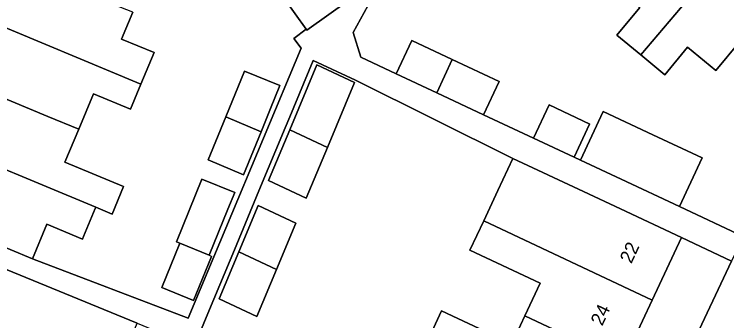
# Model space of a CAD drawing. Extents: x 159817 to 160765, y 380688 to 381638.
# Drawn here: x 160093.1 to 160145.9, y 381410.5 to 381433.2 of the extents above; entities that cross this region are included whole.
import ezdxf

# ---------------------------------------------------------------- set-up
doc = ezdxf.new("R2010")
doc.units = 0
for name, color, linetype in [('IMGEO_Erf', 7, 'Continuous'), ('IMGEO_Pand', 7, 'Continuous'), ('IMGEO_Pand_nummerreeks', 7, 'Continuous'), ('IMGEO_Voetpad_open', 7, 'Continuous')]:
    doc.layers.add(name, color=color, linetype=linetype)

msp = doc.modelspace()

# ---------------------------------------------------------------- linework, layer by layer
at = {"layer": 'IMGEO_Erf'}
for points in [[(160101.841, 381433.323), (160101.015, 381431.335), (160103.427, 381430.332), (160102.457, 381427.998), (160101.687, 381426.146), (160098.933, 381427.291), (160097.839, 381424.659), (160096.821, 381422.21), (160101.17, 381420.402), (160100.324, 381418.367), (160099.098, 381418.877), (160099.058, 381418.781), (160098.81, 381418.184), (160098.2, 381416.715), (160098.118, 381416.517), (160095.484, 381417.613), (160094.422, 381415.059), (160105.95, 381410.653), (160114.336, 381430.674), (160113.796, 381431.38), (160114.705, 381432.077), (160113.066, 381434.377)], [(160119.545, 381434.316), (160118.188, 381431.819), (160118.748, 381429.996), (160121.379, 381428.765), (160122.529, 381431.223), (160125.539, 381429.814), (160129.015, 381428.187), (160127.865, 381425.73), (160131.569, 381423.996), (160132.719, 381426.454), (160135.731, 381425.044), (160135.722, 381425.033), (160134.578, 381422.588), (160135.039, 381422.372), (160136.724, 381425.973), (160140.415, 381424.245), (160144.076, 381422.532), (160142.391, 381418.932), (160147.119, 381416.719), (160155.458, 381434.407)], [(160149.436, 381434.021), (160150.464, 381433.17), (160149.636, 381431.574), (160147.912, 381430.315), (160146.877, 381431.172), (160145.087, 381429.011), (160142.991, 381430.748), (160141.294, 381428.698), (160139.52, 381430.167), (160137.746, 381431.636), (160139.437, 381433.679)], [(160123.716, 381408.999), (160124.748, 381411.204), (160129.948, 381408.769), (160130.912, 381410.828), (160132.047, 381413.254), (160126.85, 381415.687), (160127.868, 381417.861), (160128.924, 381420.116), (160130.033, 381422.485), (160118.359, 381428.29), (160115.237, 381429.759), (160113.495, 381425.585), (160113.154, 381424.768), (160111.198, 381420.081), (160109.38, 381415.724), (160107.54, 381411.312), (160105.673, 381406.838)], [(160105.356, 381328.134), (160146.257, 381414.891), (160142.531, 381416.636), (160140.36, 381411.999), (160138.209, 381407.404), (160138.128, 381407.231), (160137.606, 381407.476), (160135.69, 381403.384), (160133.653, 381399.032), (160133.533, 381398.776), (160132.918, 381399.064), (160131.006, 381394.979), (160129.007, 381390.709), (160127.008, 381386.439), (160125.008, 381382.168), (160123.009, 381377.898), (160121.01, 381373.628), (160119.011, 381369.358), (160117.012, 381365.088)], [(160092.333, 381377.953), (160096.781, 381388.612), (160102.837, 381403.126), (160105.289, 381409.003), (160104.86, 381409.18), (160102.942, 381404.521), (160100.266, 381405.64), (160102.178, 381410.284), (160090.993, 381414.866)]]:
    msp.add_lwpolyline(points, dxfattribs=at)
for points in [[(160112.068, 381426.181), (160111.37, 381424.469), (160110.071, 381421.282), (160107.439, 381422.384), (160108.74, 381425.578), (160110.122, 381428.97), (160112.765, 381427.893)], [(160113.488, 381424.611), (160115.5, 381429.432), (160118.288, 381428.12), (160116.277, 381423.302), (160114.711, 381419.547), (160111.92, 381420.856)], [(160108.907, 381418.741), (160107.511, 381415.316), (160107.694, 381415.24), (160106.359, 381411.962), (160103.999, 381412.923), (160105.34, 381416.215), (160105.083, 381416.321), (160106.972, 381420.961), (160109.407, 381419.969)], [(160112.504, 381414.259), (160111.053, 381410.781), (160108.263, 381412.093), (160109.713, 381415.568), (160111.145, 381418.998), (160113.935, 381417.689)]]:
    msp.add_lwpolyline(points, close=True, dxfattribs=at)
at = {"layer": 'IMGEO_Pand'}
for points in [[(160143.989, 381443.336), (160139.112, 381437.447), (160137.393, 381435.371), (160139.437, 381433.679), (160137.746, 381431.636), (160139.52, 381430.167), (160147.927, 381440.075)], [(160147.927, 381440.075), (160139.52, 381430.167), (160141.294, 381428.698), (160142.991, 381430.748), (160145.087, 381429.011), (160146.877, 381431.172), (160147.912, 381430.315), (160149.636, 381431.574), (160150.464, 381433.17), (160149.436, 381434.021), (160151.796, 381436.871)], [(160102.457, 381427.998), (160103.427, 381430.332), (160101.015, 381431.335), (160101.841, 381433.323), (160100.384, 381433.89), (160100.506, 381434.184), (160092.495, 381437.537), (160090.582, 381432.936)], [(160116.153, 381436.578), (160113.066, 381434.377), (160114.705, 381432.077), (160114.765, 381431.993), (160117.852, 381434.194), (160117.745, 381434.344)], [(160088.718, 381428.451), (160095.551, 381425.61), (160097.839, 381424.659), (160098.933, 381427.291), (160101.687, 381426.146), (160102.457, 381427.998), (160090.582, 381432.936)], [(160125.539, 381429.814), (160122.529, 381431.223), (160121.379, 381428.765), (160124.388, 381427.357)], [(160125.539, 381429.814), (160124.388, 381427.357), (160127.865, 381425.73), (160129.015, 381428.187)], [(160112.068, 381426.181), (160112.765, 381427.893), (160110.122, 381428.97), (160108.74, 381425.578), (160111.37, 381424.469)], [(160118.288, 381428.12), (160115.5, 381429.432), (160113.488, 381424.611), (160116.277, 381423.302)], [(160097.839, 381424.659), (160095.551, 381425.61), (160088.718, 381428.451), (160086.854, 381423.967), (160099.098, 381418.877), (160100.324, 381418.367), (160101.17, 381420.402), (160096.821, 381422.21)], [(160135.731, 381425.044), (160132.719, 381426.454), (160131.569, 381423.996), (160134.578, 381422.588), (160135.722, 381425.033)], [(160135.039, 381422.372), (160138.055, 381420.961), (160142.391, 381418.932), (160144.076, 381422.532), (160140.415, 381424.245), (160136.724, 381425.973)], [(160111.37, 381424.469), (160108.74, 381425.578), (160107.439, 381422.384), (160110.071, 381421.282)], [(160116.277, 381423.302), (160113.488, 381424.611), (160111.92, 381420.856), (160114.711, 381419.547)], [(160099.098, 381418.877), (160086.854, 381423.967), (160084.825, 381419.086), (160084.812, 381419.054), (160089.429, 381417.135), (160094.422, 381415.059), (160095.484, 381417.613), (160098.118, 381416.517), (160098.2, 381416.715), (160098.81, 381418.184), (160099.058, 381418.781)], [(160140.36, 381411.999), (160142.531, 381416.636), (160138.003, 381418.755), (160135.264, 381420.037), (160130.033, 381422.485), (160128.924, 381420.116), (160127.868, 381417.861)], [(160109.407, 381419.969), (160106.972, 381420.961), (160105.083, 381416.321), (160105.34, 381416.215), (160107.511, 381415.316), (160108.907, 381418.741)], [(160113.935, 381417.689), (160111.145, 381418.998), (160109.713, 381415.568), (160112.504, 381414.259)], [(160130.912, 381410.828), (160138.209, 381407.404), (160140.36, 381411.999), (160127.868, 381417.861), (160126.85, 381415.687), (160132.047, 381413.254)], [(160107.511, 381415.316), (160105.34, 381416.215), (160103.999, 381412.923), (160106.359, 381411.962), (160107.694, 381415.24)], [(160112.504, 381414.259), (160109.713, 381415.568), (160108.263, 381412.093), (160111.053, 381410.781)], [(160123.716, 381408.999), (160135.69, 381403.384), (160137.606, 381407.476), (160138.128, 381407.231), (160138.209, 381407.404), (160130.912, 381410.828), (160129.948, 381408.769), (160124.748, 381411.204)]]:
    msp.add_lwpolyline(points, close=True, dxfattribs=at)
at = {"layer": 'IMGEO_Voetpad_open'}
for points in [[(160158.462, 381438.892), (160156.601, 381436.871), (160155.458, 381434.407), (160147.119, 381416.719), (160146.257, 381414.891), (160105.356, 381328.134), (160109.962, 381325.916)], [(160147.119, 381416.719), (160142.391, 381418.932), (160138.055, 381420.961), (160135.039, 381422.372), (160134.578, 381422.588), (160131.569, 381423.996), (160127.865, 381425.73), (160124.388, 381427.357), (160121.379, 381428.765), (160118.748, 381429.996), (160118.188, 381431.819), (160119.545, 381434.316)], [(160117.852, 381434.194), (160114.765, 381431.993), (160114.705, 381432.077), (160113.796, 381431.38), (160114.336, 381430.674), (160105.95, 381410.653), (160094.422, 381415.059), (160089.429, 381417.135)], [(160093.015, 381376.502), (160094.77, 381380.707), (160096.588, 381385.063), (160098.404, 381389.416), (160100.222, 381393.773), (160102.039, 381398.128), (160103.857, 381402.485), (160105.673, 381406.838), (160107.54, 381411.312), (160109.38, 381415.724), (160111.198, 381420.081), (160113.154, 381424.768), (160113.495, 381425.585), (160115.237, 381429.759), (160118.359, 381428.29), (160130.033, 381422.485), (160135.264, 381420.037), (160138.003, 381418.755), (160142.531, 381416.636), (160146.257, 381414.891)], [(160090.993, 381414.866), (160102.178, 381410.284), (160104.86, 381409.18), (160105.289, 381409.003), (160102.837, 381403.126), (160096.781, 381388.612), (160092.333, 381377.953)]]:
    msp.add_lwpolyline(points, dxfattribs=at)

# ---------------------------------------------------------------- texts
at = {"layer": 'IMGEO_Pand_nummerreeks'}
for s, p in [('22', (160138.816, 381414.646)), ('24', (160136.657, 381410.033))]:
    msp.add_text(s, height=1, rotation=64.9131, dxfattribs=at).set_placement(p)

doc.saveas('drawing.dxf')
